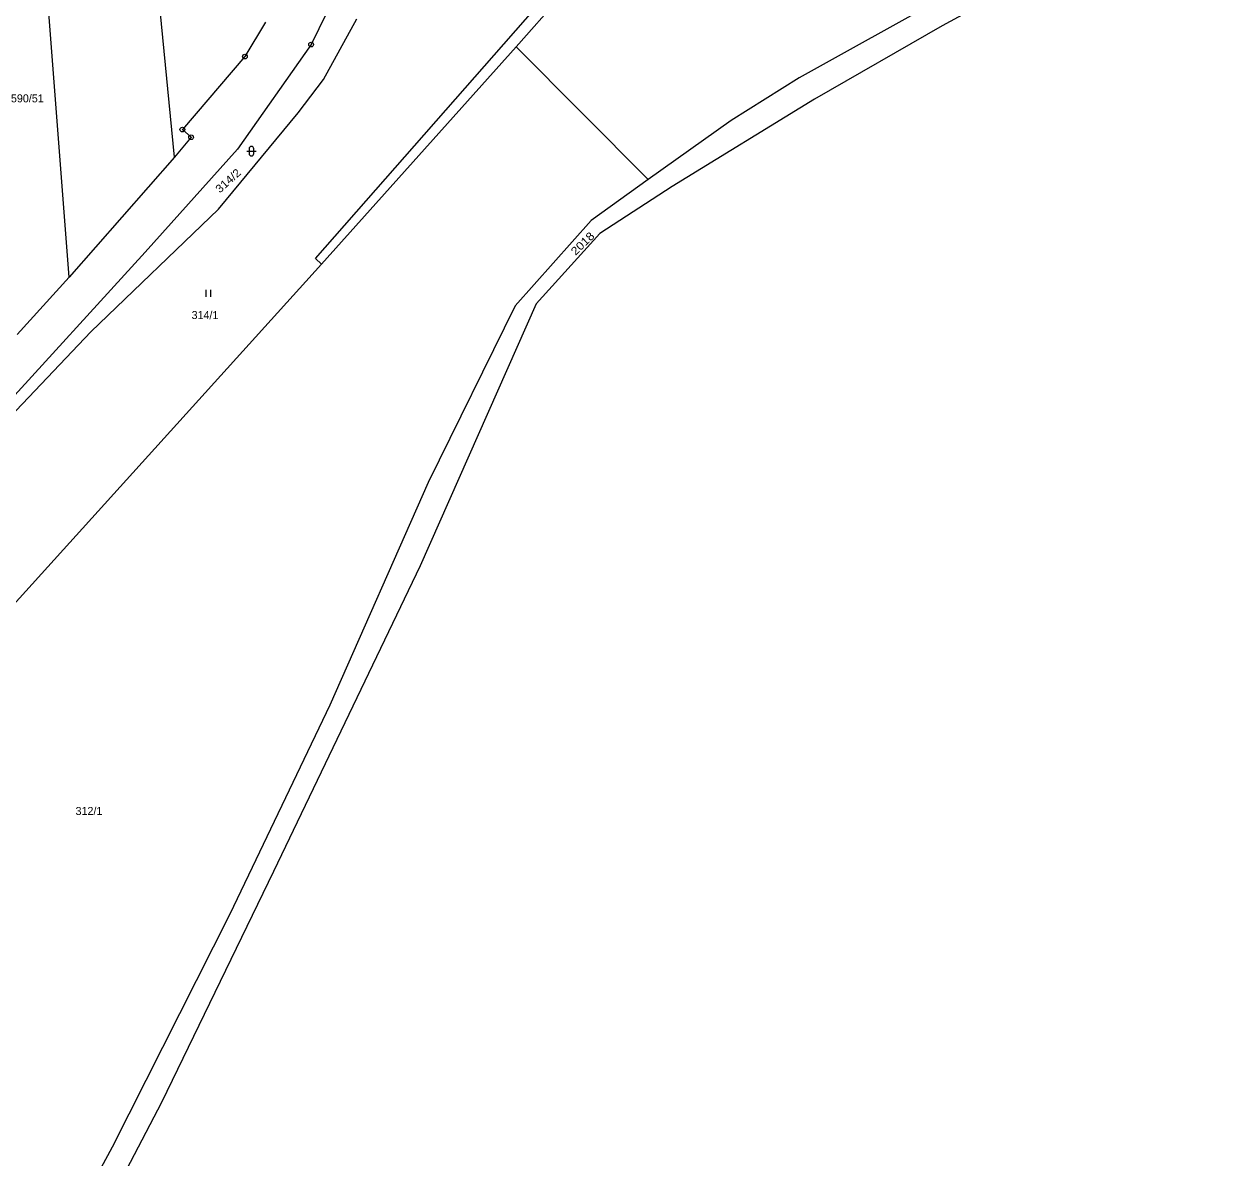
# Model space of a CAD drawing. Extents: x -820420 to -815896, y -1105820 to -1103643.
# Drawn here: x -816371.7 to -816116.3, y -1104801.1 to -1104560.1 of the extents above; entities that cross this region are included whole.
import ezdxf
from ezdxf.enums import TextEntityAlignment as Align

# ---------------------------------------------------------------- set-up
doc = ezdxf.new("R2010")
doc.units = 0
doc.header["$LTSCALE"] = 0.68
for name, color, linetype, lineweight in [('1', 7, 'Continuous', 25), ('3', 7, 'Continuous', 25), ('8', 7, 'Continuous', 25)]:
    doc.layers.add(name, color=color, linetype=linetype, lineweight=lineweight)
doc.layers.add('2', color=7, linetype='Continuous')

msp = doc.modelspace()

# ---------------------------------------------------------------- linework, layer by layer
at = {"layer": '1'}
for p, q in [((-816309.8, -1104609.98), (-816210.12, -1104496.27)), ((-816267.24, -1104564.98), (-816208.66, -1104498.96)), ((-816116.27, -1104527.45), (-816176.77, -1104560.56)), ((-816301, -1104544.36), (-816310.75, -1104564.5)), ((-816167.88, -1104549.73), (-816207.09, -1104571.58)), ((-816362.12, -1104613.91), (-816366.67, -1104554.94)), ((-816339.8, -1104588.42), (-816342.79, -1104557.17)), ((-816308.12, -1104571.94), (-816301.06, -1104559.01)), ((-816320.42, -1104559.73), (-816324.82, -1104567.07)), ((-816176.77, -1104560.56), (-816203.86, -1104576.08)), ((-816310.75, -1104564.5), (-816326.36, -1104586.7)), ((-816267.24, -1104564.98), (-816308.58, -1104611.14)), ((-816267.24, -1104564.98), (-816239.17, -1104593.2)), ((-816324.82, -1104567.07), (-816338.1, -1104582.56)), ((-816313.51, -1104579), (-816308.12, -1104571.94)), ((-816207.09, -1104571.58), (-816221.53, -1104580.62)), ((-816203.86, -1104576.08), (-816234.06, -1104594.69)), ((-816330.41, -1104599.45), (-816313.51, -1104579)), ((-816221.53, -1104580.62), (-816239.17, -1104593.2)), ((-816336.23, -1104584.21), (-816339.8, -1104588.42)), ((-816338.1, -1104582.56), (-816336.23, -1104584.21)), ((-816326.36, -1104586.7), (-816345.97, -1104608.59)), ((-816239.17, -1104593.2), (-816251.31, -1104601.92)), ((-816234.06, -1104594.69), (-816249.46, -1104604.67)), ((-816357.51, -1104625.56), (-816330.41, -1104599.45)), ((-816251.31, -1104601.92), (-816267.41, -1104620.01)), ((-816249.46, -1104604.67), (-816262.97, -1104619.58)), ((-816345.97, -1104608.59), (-816378.68, -1104644.45)), ((-816308.58, -1104611.14), (-816309.8, -1104609.98)), ((-816439.41, -1104756.01), (-816308.58, -1104611.14)), ((-816262.97, -1104619.58), (-816287.6, -1104675.28)), ((-816267.41, -1104620.01), (-816285.89, -1104657.57)), ((-816379.81, -1104648.99), (-816357.51, -1104625.56)), ((-816285.89, -1104657.57), (-816306.77, -1104704.85)), ((-816287.6, -1104675.28), (-816318.74, -1104740.21)), ((-816306.77, -1104704.85), (-816328, -1104749.26)), ((-816318.74, -1104740.21), (-816342.54, -1104789.29)), ((-816328, -1104749.26), (-816353.02, -1104798.84)), ((-816342.54, -1104789.29), (-816356.48, -1104815.93)), ((-816353.02, -1104798.84), (-816362.9, -1104817.21))]:
    msp.add_line(p, q, dxfattribs=at)
msp.add_lwpolyline([(-816339.8, -1104588.42), (-816362.12, -1104613.91), (-816373.16, -1104626.11)], dxfattribs=at)
at = {"layer": '3'}
for p, q in [((-816324.421, -1104587.161), (-816322.419, -1104587.161)), ((-816323.921, -1104586.661), (-816323.921, -1104587.662)), ((-816322.919, -1104587.662), (-816322.919, -1104586.661)), ((-816333.021, -1104618.1), (-816333.021, -1104616.6)), ((-816332.02, -1104618.1), (-816332.02, -1104616.6))]:
    msp.add_line(p, q, dxfattribs=at)
for centre, start, end in [((-816323.42, -1104586.6609), 0, 180), ((-816323.42, -1104587.6609), 180, 359.98789)]:
    msp.add_arc(centre, 0.5, start, end, dxfattribs=at)
at = {"layer": '8'}
for centre, radius in [((-816310.75, -1104564.4999), 0.5), ((-816310.75, -1104564.4999), 0.0303), ((-816324.82, -1104567.0699), 0.5), ((-816324.82, -1104567.0699), 0.0303), ((-816338.1, -1104582.5599), 0.5), ((-816338.1, -1104582.5599), 0.0303), ((-816336.23, -1104584.2099), 0.5), ((-816336.23, -1104584.2099), 0.0303)]:
    msp.add_circle(centre, radius, dxfattribs=at)

# ---------------------------------------------------------------- texts
at = {"layer": '2'}
for s, p in [('590/51', (-816371.02, -1104576.785)), ('314/1', (-816333.29, -1104622.835)), ('312/1', (-816357.93, -1104728.215))]:
    msp.add_text(s, height=1.7, dxfattribs=at).set_placement(p, align=Align.CENTER)
for s, rotation, width, p in [('314/2', 42, 1.1, (-816327.8158, -1104594.0645)), ('2018', 44, 1.15, (-816252.5135, -1104607.395))]:
    msp.add_text(s, height=1.7, rotation=rotation, dxfattribs=dict(at, width=width)).set_placement(p, align=Align.CENTER)

doc.saveas('drawing.dxf')
